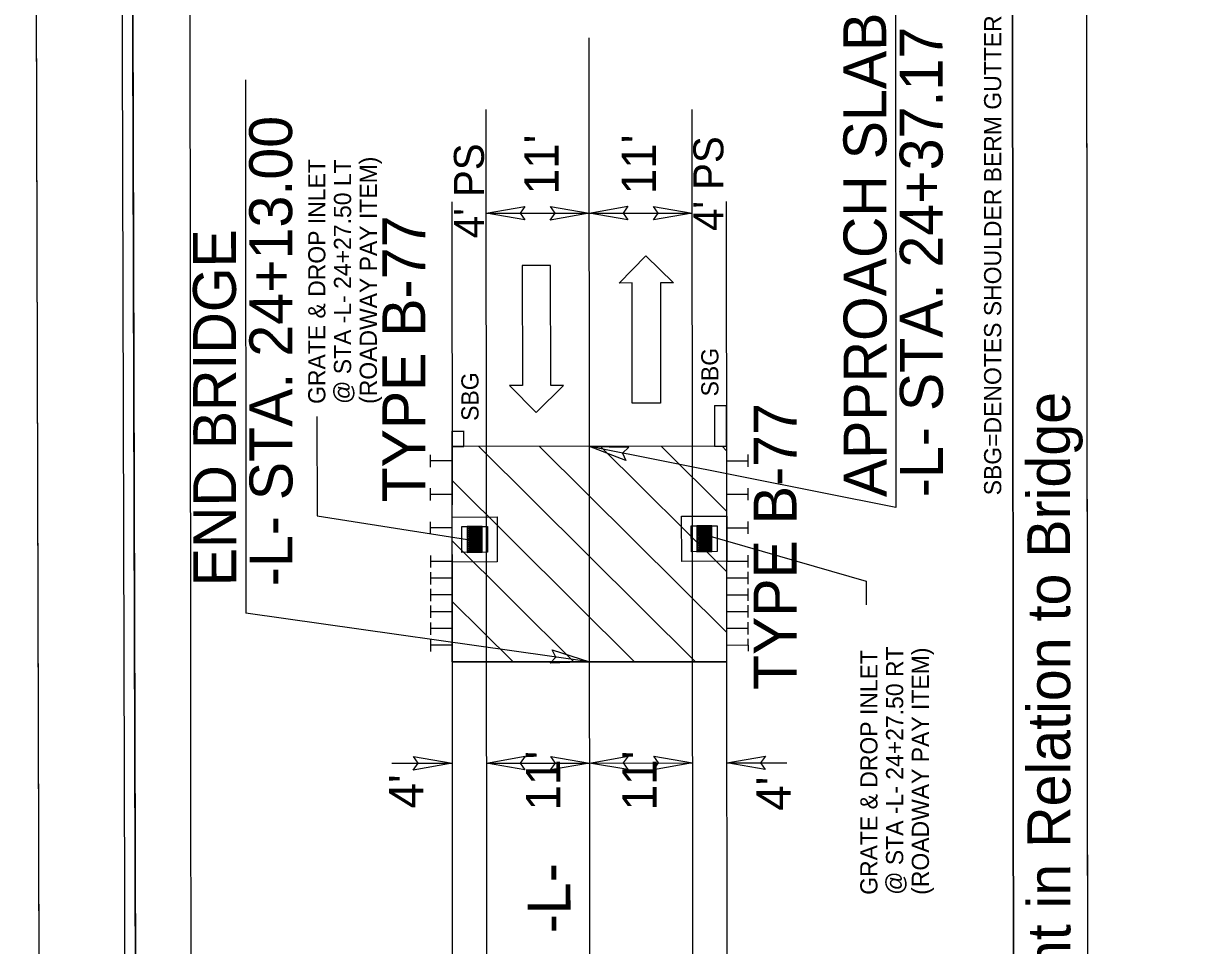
# Model space of a CAD drawing. Extents: x 1373110 to 1374209, y 550682 to 552749.
# Drawn here: x 1373109.6 to 1373384.5, y 551240.4 to 551455.3 of the extents above; entities that cross this region are included whole.
import ezdxf

# ---------------------------------------------------------------- set-up
doc = ezdxf.new("R2010")
doc.units = 0
for name, color, linetype in [('Default', 7, 'Continuous'), ('Prop Approach Slab Hatching', 7, 'Continuous'), ('Prop Drainage Structure Drop Inlet Grate 2 Narrow Slots and Flat Grates 840 29 TB Label', 7, 'Continuous'), ('Prop Drainage Structure Gutter Shoulder Berm Label', 7, 'Continuous'), ('Prop Drainage Structure Pipe Alternate 18in', 7, 'Continuous'), ('Prop Drainage Structure Pipe Alternate 18in Label', 7, 'Continuous'), ('Prop Drainage Structure Pipe CSP 15in Label', 7, 'Continuous'), ('Prop Drainage Structure Pipe RCP 15in Class IV Label', 7, 'Continuous'), ('Prop Drainage Structure Pipe Removal Label', 7, 'Continuous'), ('Prop Drainage Structure Tops and Inverts LABEL', 7, 'Continuous'), ('Prop Earthen Structure Base Ditch with Rip Rap Detail CELL', 7, 'Continuous'), ('Prop Earthen Structure Base Ditch with Rip Rap Detail Label', 7, 'Continuous'), ('Prop Earthen Structure V Ditch Special Lateral Detail Label', 7, 'Continuous'), ('Prop Erosion Rip Rap At Embankment Detail CELL', 7, 'Continuous'), ('Prop Erosion Rip Rap At Embankment Detail Label', 7, 'Continuous'), ('Prop Erosion Rip Rap Class B Label', 7, 'Continuous'), ('Prop Erosion Rip Rap Class I', 7, 'Continuous'), ('Prop Plan Preparation Sketches Hydraulic Ditch', 7, 'Continuous'), ('Prop Roadway Bridge', 7, 'Continuous'), ('Prop SS Fill Line', 7, 'Continuous')]:
    doc.layers.add(name, color=color, linetype=linetype)

msp = doc.modelspace()

# ---------------------------------------------------------------- linework, layer by layer
at = {"layer": 'Default'}
for p, q in [((1373216.4, 551338.01), (1373212.9, 551338)), ((1373212.9, 551338), (1373212.91, 551332)), ((1373212.99, 551337.91), (1373216.3, 551337.92)), ((1373213.01, 551332.1), (1373212.99, 551337.91)), ((1373216.29, 551337.9), (1373213, 551337.89)), ((1373213, 551337.89), (1373213.01, 551335.02)), ((1373213.28, 551337.38), (1373213.28, 551337.65)), ((1373213.28, 551337.65), (1373216.01, 551337.65)), ((1373216.01, 551337.39), (1373213.28, 551337.38)), ((1373213.28, 551337.2), (1373216.01, 551337.21)), ((1373213.28, 551336.93), (1373213.28, 551337.2)), ((1373214.65, 551338.01), (1373214.65, 551338.01)), ((1373216.01, 551337.65), (1373216.01, 551337.39)), ((1373216.01, 551337.21), (1373216.02, 551336.94)), ((1373216.29, 551335.03), (1373216.29, 551337.9)), ((1373216.3, 551337.92), (1373216.32, 551332.11)), ((1373216.41, 551332.01), (1373216.4, 551338.01)), ((1373269.9, 551338.17), (1373266.4, 551338.16)), ((1373266.4, 551338.16), (1373266.41, 551332.16)), ((1373266.49, 551338.07), (1373269.8, 551338.08)), ((1373266.51, 551332.26), (1373266.49, 551338.07)), ((1373269.79, 551338.06), (1373266.5, 551338.05)), ((1373266.5, 551338.05), (1373266.51, 551335.18)), ((1373266.78, 551337.8), (1373269.51, 551337.81)), ((1373266.78, 551337.54), (1373266.78, 551337.8)), ((1373269.51, 551337.55), (1373266.78, 551337.54)), ((1373266.78, 551337.36), (1373269.51, 551337.37)), ((1373266.78, 551337.09), (1373266.78, 551337.36)), ((1373268.15, 551338.17), (1373268.15, 551338.17)), ((1373269.51, 551337.81), (1373269.51, 551337.55)), ((1373269.51, 551337.37), (1373269.52, 551337.1)), ((1373269.79, 551335.19), (1373269.79, 551338.06)), ((1373269.8, 551338.08), (1373269.82, 551332.27)), ((1373269.91, 551332.17), (1373269.9, 551338.17)), ((1373212.9, 551335), (1373212.9, 551335)), ((1373213.01, 551335.02), (1373216.29, 551335.03)), ((1373216.29, 551335), (1373213.01, 551334.99)), ((1373213.01, 551334.99), (1373213.02, 551332.11)), ((1373216.02, 551336.94), (1373213.28, 551336.93)), ((1373213.28, 551336.75), (1373216.02, 551336.76)), ((1373213.28, 551336.49), (1373213.28, 551336.75)), ((1373216.02, 551336.5), (1373213.28, 551336.49)), ((1373213.28, 551336.31), (1373216.02, 551336.32)), ((1373213.28, 551336.04), (1373213.28, 551336.31)), ((1373216.02, 551336.05), (1373213.28, 551336.04)), ((1373213.28, 551335.86), (1373216.02, 551335.87)), ((1373213.28, 551335.6), (1373213.28, 551335.86)), ((1373216.02, 551335.61), (1373213.28, 551335.6)), ((1373213.29, 551335.42), (1373216.02, 551335.43)), ((1373213.29, 551335.15), (1373213.29, 551335.42)), ((1373216.02, 551335.16), (1373213.29, 551335.15)), ((1373213.29, 551334.59), (1373213.29, 551334.86)), ((1373213.29, 551334.86), (1373216.02, 551334.86)), ((1373216.02, 551334.6), (1373213.29, 551334.59)), ((1373213.29, 551334.41), (1373216.02, 551334.42)), ((1373213.29, 551334.15), (1373213.29, 551334.41)), ((1373214.65, 551335.01), (1373214.65, 551335.01)), ((1373216.02, 551336.76), (1373216.02, 551336.5)), ((1373216.02, 551336.32), (1373216.02, 551336.05)), ((1373216.02, 551335.87), (1373216.02, 551335.61)), ((1373216.02, 551335.43), (1373216.02, 551335.16)), ((1373216.02, 551334.86), (1373216.02, 551334.6)), ((1373216.02, 551334.42), (1373216.02, 551334.15)), ((1373216.3, 551332.12), (1373216.29, 551335)), ((1373216.4, 551335.01), (1373216.4, 551335.01)), ((1373266.4, 551335.16), (1373266.4, 551335.16)), ((1373266.51, 551335.18), (1373269.79, 551335.19)), ((1373269.79, 551335.16), (1373266.51, 551335.15)), ((1373266.51, 551335.15), (1373266.52, 551332.27)), ((1373269.52, 551337.1), (1373266.78, 551337.09)), ((1373266.78, 551336.91), (1373269.52, 551336.92)), ((1373266.78, 551336.65), (1373266.78, 551336.91)), ((1373269.52, 551336.66), (1373266.78, 551336.65)), ((1373266.78, 551336.47), (1373269.52, 551336.48)), ((1373266.78, 551336.2), (1373266.78, 551336.47)), ((1373269.52, 551336.21), (1373266.78, 551336.2)), ((1373266.78, 551336.02), (1373269.52, 551336.03)), ((1373266.78, 551335.76), (1373266.78, 551336.02)), ((1373269.52, 551335.77), (1373266.78, 551335.76)), ((1373266.79, 551335.58), (1373269.52, 551335.59)), ((1373266.79, 551335.31), (1373266.79, 551335.58)), ((1373269.52, 551335.32), (1373266.79, 551335.31)), ((1373266.79, 551334.75), (1373266.79, 551335.02)), ((1373266.79, 551335.02), (1373269.52, 551335.02)), ((1373269.52, 551334.76), (1373266.79, 551334.75)), ((1373266.79, 551334.57), (1373269.52, 551334.58)), ((1373266.79, 551334.3), (1373266.79, 551334.57)), ((1373268.15, 551335.17), (1373268.15, 551335.17)), ((1373269.52, 551336.92), (1373269.52, 551336.66)), ((1373269.52, 551336.48), (1373269.52, 551336.21)), ((1373269.52, 551336.03), (1373269.52, 551335.77)), ((1373269.52, 551335.59), (1373269.52, 551335.32)), ((1373269.52, 551335.02), (1373269.52, 551334.76)), ((1373269.52, 551334.58), (1373269.52, 551334.31)), ((1373269.8, 551332.28), (1373269.79, 551335.16)), ((1373269.9, 551335.17), (1373269.9, 551335.17)), ((1373212.91, 551332), (1373216.41, 551332.01)), ((1373216.32, 551332.11), (1373213.01, 551332.1)), ((1373213.02, 551332.11), (1373216.3, 551332.12)), ((1373216.02, 551334.15), (1373213.29, 551334.15)), ((1373213.29, 551333.7), (1373213.29, 551333.97)), ((1373213.29, 551333.97), (1373216.02, 551333.97)), ((1373216.02, 551333.71), (1373213.29, 551333.7)), ((1373213.29, 551333.52), (1373216.02, 551333.53)), ((1373213.29, 551333.26), (1373213.29, 551333.52)), ((1373216.03, 551333.26), (1373213.29, 551333.26)), ((1373213.29, 551332.81), (1373213.29, 551333.08)), ((1373213.29, 551333.08), (1373216.03, 551333.08)), ((1373216.03, 551332.82), (1373213.29, 551332.81)), ((1373213.29, 551332.63), (1373216.03, 551332.64)), ((1373213.29, 551332.36), (1373213.29, 551332.63)), ((1373216.03, 551332.37), (1373213.29, 551332.36)), ((1373214.66, 551332.01), (1373214.66, 551332.01)), ((1373216.02, 551333.97), (1373216.02, 551333.71)), ((1373216.02, 551333.53), (1373216.03, 551333.26)), ((1373216.03, 551333.08), (1373216.03, 551332.82)), ((1373216.03, 551332.64), (1373216.03, 551332.37)), ((1373266.41, 551332.16), (1373269.91, 551332.17)), ((1373269.82, 551332.27), (1373266.51, 551332.26)), ((1373266.52, 551332.27), (1373269.8, 551332.28)), ((1373269.52, 551334.31), (1373266.79, 551334.3)), ((1373266.79, 551334.12), (1373269.52, 551334.13)), ((1373266.79, 551333.86), (1373266.79, 551334.12)), ((1373269.52, 551333.87), (1373266.79, 551333.86)), ((1373266.79, 551333.68), (1373269.52, 551333.69)), ((1373266.79, 551333.41), (1373266.79, 551333.68)), ((1373269.53, 551333.42), (1373266.79, 551333.41)), ((1373266.79, 551333.23), (1373269.53, 551333.24)), ((1373266.79, 551332.97), (1373266.79, 551333.23)), ((1373269.53, 551332.98), (1373266.79, 551332.97)), ((1373266.79, 551332.79), (1373269.53, 551332.8)), ((1373266.79, 551332.52), (1373266.79, 551332.79)), ((1373269.53, 551332.53), (1373266.79, 551332.52)), ((1373268.16, 551332.17), (1373268.16, 551332.17)), ((1373269.52, 551334.13), (1373269.52, 551333.87)), ((1373269.52, 551333.69), (1373269.53, 551333.42)), ((1373269.53, 551333.24), (1373269.53, 551332.98)), ((1373269.53, 551332.8), (1373269.53, 551332.53))]:
    msp.add_line(p, q, dxfattribs=at)
for points in [[(1373219.89, 551340.27), (1373219.92, 551329.77), (1373209.42, 551329.74), (1373209.39, 551340.24)], [(1373273.39, 551340.43), (1373273.42, 551329.93), (1373262.92, 551329.9), (1373262.89, 551340.4)], [(1373217.65, 551338.02), (1373217.66, 551332.02), (1373211.66, 551332), (1373211.65, 551338)], [(1373271.15, 551338.18), (1373271.16, 551332.18), (1373265.16, 551332.16), (1373265.15, 551338.16)]]:
    msp.add_lwpolyline(points, close=True, dxfattribs=at)
at = {"layer": 'Prop Approach Slab Hatching'}
for p, q in [((1373273.44, 551306.49), (1373209.4, 551306.44)), ((1373209.4, 551306.44), (1373209.49, 551206.85)), ((1373273.53, 551206.9), (1373273.44, 551306.49))]:
    msp.add_line(p, q, dxfattribs=at)
at = {"layer": 'Prop Drainage Structure Drop Inlet Grate 2 Narrow Slots and Flat Grates 840 29 TB Label'}
for points in [[(1373132.1, 552509.76), (1373136.2, 551009.73), (1374186.2, 551012.6), (1374182.1, 552512.6)], [(1374186.2, 551012.6), (1373136.23, 551009.7), (1373132.64, 552309.68), (1373282.7, 552310.11), (1373282.16, 552510.14), (1374182.1, 552512.6)]]:
    msp.add_lwpolyline(points, close=True, dxfattribs=at)
at = {"layer": 'Prop Drainage Structure Gutter Shoulder Berm Label'}
msp.add_lwpolyline([(1374209.17, 550846.17), (1374204.56, 552529.67), (1373109.57, 552526.67), (1373114.17, 550843.18)], close=True, dxfattribs=at)
at = {"layer": 'Prop Drainage Structure Pipe Alternate 18in'}
for p, q in [((1373204.4, 551351.88), (1373204.4, 551354.74)), ((1373278.4, 551351.94), (1373278.4, 551354.81)), ((1373209.4, 551353.31), (1373204.4, 551353.31)), ((1373209.44, 551306.44), (1373209.4, 551353.31)), ((1373273.4, 551353.37), (1373278.4, 551353.37)), ((1373273.44, 551306.49), (1373273.4, 551353.37)), ((1373204.41, 551344.06), (1373204.4, 551346.93)), ((1373209.4, 551345.5), (1373204.4, 551345.5)), ((1373273.4, 551345.56), (1373278.4, 551345.56)), ((1373278.41, 551344.13), (1373278.4, 551346.99)), ((1373204.41, 551336.25), (1373204.41, 551339.12)), ((1373209.41, 551337.69), (1373204.41, 551337.68)), ((1373273.41, 551337.74), (1373278.41, 551337.75)), ((1373278.41, 551336.32), (1373278.41, 551339.18)), ((1373204.42, 551328.44), (1373204.42, 551331.3)), ((1373209.42, 551329.88), (1373204.42, 551329.87)), ((1373273.42, 551329.93), (1373278.42, 551329.94)), ((1373278.42, 551328.5), (1373278.42, 551331.37)), ((1373204.42, 551324.53), (1373204.42, 551327.4)), ((1373278.42, 551324.6), (1373278.42, 551327.46)), ((1373209.42, 551325.97), (1373204.42, 551325.96)), ((1373204.43, 551320.63), (1373204.42, 551323.49)), ((1373273.42, 551326.03), (1373278.42, 551326.03)), ((1373278.43, 551320.69), (1373278.42, 551323.56)), ((1373209.42, 551322.06), (1373204.42, 551322.06)), ((1373273.42, 551322.12), (1373278.42, 551322.12)), ((1373204.43, 551316.72), (1373204.43, 551319.58)), ((1373209.43, 551318.16), (1373204.43, 551318.15)), ((1373273.43, 551318.21), (1373278.43, 551318.22)), ((1373278.43, 551316.79), (1373278.43, 551319.65)), ((1373204.43, 551312.81), (1373204.43, 551315.68)), ((1373278.43, 551312.88), (1373278.43, 551315.74)), ((1373209.43, 551314.25), (1373204.43, 551314.25)), ((1373273.43, 551314.31), (1373278.43, 551314.31)), ((1373204.44, 551308.91), (1373204.43, 551311.77)), ((1373209.43, 551310.34), (1373204.43, 551310.34)), ((1373273.43, 551310.4), (1373278.43, 551310.41)), ((1373278.44, 551308.97), (1373278.43, 551311.84))]:
    msp.add_line(p, q, dxfattribs=at)
at = {"layer": 'Prop Drainage Structure Pipe Alternate 18in Label'}
for points in [[(1373226.35, 551409.52), (1373217.35, 551411.06), (1373226.39, 551412.67), (1373225.25, 551411.07)], [(1373232.34, 551412.62), (1373241.35, 551411.08), (1373232.3, 551409.47), (1373233.45, 551411.07)], [(1373250.35, 551409.54), (1373241.35, 551411.08), (1373250.39, 551412.69), (1373249.25, 551411.09)], [(1373256.34, 551412.64), (1373265.35, 551411.1), (1373256.3, 551409.49), (1373257.45, 551411.09)], [(1373249.92, 551353.42), (1373241.39, 551356.7), (1373250.58, 551356.5), (1373249.14, 551355.16)], [(1373232.74, 551309.26), (1373241.44, 551306.47), (1373232.25, 551306.15), (1373233.62, 551307.57)], [(1373200.38, 551284.4), (1373209.39, 551282.86), (1373200.34, 551281.25), (1373201.49, 551282.85)], [(1373226.39, 551281.32), (1373217.39, 551282.86), (1373226.43, 551284.47), (1373225.29, 551282.87)], [(1373232.38, 551284.43), (1373241.39, 551282.88), (1373232.34, 551281.28), (1373233.49, 551282.88)], [(1373250.39, 551281.34), (1373241.39, 551282.88), (1373250.43, 551284.49), (1373249.29, 551282.89)], [(1373256.38, 551284.45), (1373265.39, 551282.9), (1373256.34, 551281.3), (1373257.49, 551282.9)], [(1373282.39, 551281.37), (1373273.39, 551282.91), (1373282.43, 551284.52), (1373281.29, 551282.92)]]:
    msp.add_lwpolyline(points, close=True, dxfattribs=at)
at = {"layer": 'Prop Drainage Structure Pipe CSP 15in Label'}
msp.add_line((1373109.57, 552526.67), (1373114.17, 550843.18), dxfattribs=at)
at = {"layer": 'Prop Drainage Structure Pipe RCP 15in Class IV Label'}
msp.add_lwpolyline([(1373136.23, 551009.7), (1374186.2, 551012.6), (1374182.1, 552512.59), (1373343.59, 552510.3), (1373344.24, 552271.05), (1373132.76, 552270.47)], close=True, dxfattribs=at)
at = {"layer": 'Prop Drainage Structure Pipe Removal Label'}
for p, q in [((1373209.34, 551413.72), (1373209.41, 551343.09)), ((1373273.41, 551343.15), (1373273.34, 551413.77))]:
    msp.add_line(p, q, dxfattribs=at)
at = {"layer": 'Prop Drainage Structure Tops and Inverts LABEL'}
msp.add_lwpolyline([(1374189.13, 550859.12), (1374184.56, 552525.1), (1373129.58, 552522.23), (1373134.14, 550856.23)], close=True, dxfattribs=at)
at = {"layer": 'Prop Earthen Structure Base Ditch with Rip Rap Detail CELL'}
msp.add_lwpolyline([(1374186.06, 551062.6), (1374182.23, 552462.6), (1373343.73, 552460.31), (1373344.24, 552271.05), (1373132.76, 552270.47), (1373136.07, 551059.72)], close=True, dxfattribs=at)
at = {"layer": 'Prop Earthen Structure Base Ditch with Rip Rap Detail Label'}
for p, q in [((1373177.89, 551363.69), (1373177.95, 551340.49)), ((1373177.95, 551340.49), (1373213.01, 551335.02)), ((1373269.52, 551335.77), (1373305.87, 551325.25)), ((1373305.87, 551325.25), (1373305.89, 551319.74))]:
    msp.add_line(p, q, dxfattribs=at)
at = {"layer": 'Prop Earthen Structure V Ditch Special Lateral Detail Label'}
for p, q in [((1373217.64, 551078.27), (1373217.32, 551435.22)), ((1373265.64, 551078.31), (1373265.32, 551435.27))]:
    msp.add_line(p, q, dxfattribs=at)
at = {"layer": 'Prop Erosion Rip Rap At Embankment Detail CELL'}
for p, q in [((1373270.54, 551366.24), (1373273.37, 551366.25)), ((1373270.54, 551366.24), (1373270.57, 551356.72)), ((1373273.36, 551356.73), (1373273.35, 551366.25)), ((1373209.35, 551360.22), (1373209.36, 551356.67)), ((1373209.39, 551360.22), (1373212.21, 551360.22)), ((1373212.15, 551356.68), (1373212.14, 551360.22)), ((1373209.36, 551356.67), (1373212.15, 551356.68)), ((1373270.57, 551356.72), (1373273.36, 551356.73))]:
    msp.add_line(p, q, dxfattribs=at)
at = {"layer": 'Prop Erosion Rip Rap At Embankment Detail Label'}
for p, q in [((1373273.39, 551356.73), (1373209.36, 551356.67)), ((1373209.36, 551356.67), (1373209.4, 551306.44)), ((1373273.44, 551306.49), (1373273.39, 551356.73)), ((1373209.4, 551306.44), (1373273.44, 551306.49)), ((1373273.44, 551306.49), (1373209.44, 551306.44))]:
    msp.add_line(p, q, dxfattribs=at)
at = {"layer": 'Prop Erosion Rip Rap Class B Label'}
for points in [[(1374186.06, 551062.6), (1374182.23, 552462.6), (1373343.73, 552460.31), (1373344.24, 552271.05), (1373132.76, 552270.47), (1373136.07, 551059.72)], [(1374186.13, 551055.1), (1374185.31, 551891.66), (1374039.33, 551891.53), (1374038.82, 552461.52), (1373346.29, 552460.9), (1373346.46, 552271.64), (1373134.97, 552271.45), (1373135.76, 551468.67), (1373357.23, 551468.89), (1373357.64, 551054.29)]]:
    msp.add_lwpolyline(points, close=True, dxfattribs=at)
at = {"layer": 'Prop Erosion Rip Rap Class I'}
for p, q in [((1373248.37, 551394.79), (1373254.57, 551401.1)), ((1373254.57, 551401.1), (1373260.97, 551394.8)), ((1373225.75, 551398.89), (1373225.78, 551370.89)), ((1373232.35, 551398.89), (1373225.75, 551398.89)), ((1373232.38, 551370.89), (1373232.35, 551398.89)), ((1373251.37, 551394.8), (1373248.37, 551394.79)), ((1373251.4, 551366.8), (1373251.37, 551394.8)), ((1373260.97, 551394.8), (1373257.97, 551394.8)), ((1373257.97, 551394.8), (1373258, 551366.8)), ((1373225.78, 551370.89), (1373222.78, 551370.88)), ((1373222.78, 551370.88), (1373228.99, 551364.59)), ((1373228.99, 551364.59), (1373235.38, 551370.89)), ((1373235.38, 551370.89), (1373232.38, 551370.89)), ((1373258, 551366.8), (1373251.4, 551366.8))]:
    msp.add_line(p, q, dxfattribs=at)
at = {"layer": 'Prop Plan Preparation Sketches Hydraulic Ditch'}
for p, q in [((1373312.7, 551466.02), (1373312.81, 551342.47)), ((1373161.27, 551442.19), (1373161.38, 551317.8)), ((1373217.35, 551411.06), (1373241.35, 551411.08)), ((1373241.35, 551411.08), (1373265.35, 551411.1)), ((1373312.81, 551342.47), (1373241.39, 551356.7)), ((1373241.44, 551306.47), (1373161.38, 551317.8)), ((1373195.39, 551282.84), (1373209.39, 551282.86)), ((1373217.39, 551282.86), (1373241.39, 551282.88)), ((1373241.39, 551282.88), (1373265.39, 551282.9)), ((1373273.39, 551282.91), (1373287.39, 551282.92))]:
    msp.add_line(p, q, dxfattribs=at)
for points in [[(1373148.78, 551044.12), (1373148.41, 551468.7), (1373340.01, 551468.88), (1373340.39, 551044.29)], [(1373340.39, 551044.29), (1373340.01, 551468.88), (1373357.23, 551468.89), (1373357.61, 551044.31)]]:
    msp.add_lwpolyline(points, close=True, dxfattribs=at)
at = {"layer": 'Prop Roadway Bridge'}
msp.add_line((1373241.66, 551054.35), (1373241.31, 551451.98), dxfattribs=at)
at = {"layer": 'Prop SS Fill Line'}
for p, q in [((1373266.11, 551306.49), (1373215.65, 551356.68)), ((1373273.43, 551313.32), (1373229.81, 551356.69)), ((1373273.4, 551327.44), (1373243.98, 551356.7)), ((1373273.38, 551341.57), (1373258.15, 551356.72)), ((1373273.36, 551355.7), (1373272.32, 551356.73)), ((1373251.94, 551306.48), (1373209.37, 551348.82)), ((1373223.55, 551320.61), (1373209.39, 551334.69)), ((1373216.49, 551313.53), (1373209.42, 551320.56)), ((1373237.78, 551306.46), (1373223.56, 551320.61)), ((1373223.61, 551306.45), (1373216.5, 551313.52)), ((1373209.44, 551306.44), (1373209.42, 551306.46)), ((1373209.44, 551306.44), (1373209.44, 551306.44))]:
    msp.add_line(p, q, dxfattribs=at)

# ---------------------------------------------------------------- texts
at = {"layer": 'Prop Drainage Structure Pipe Alternate 18in'}
for p in [(1373203.17, 551343.64), (1373289.67, 551299.92)]:
    msp.add_text('TYPE B-77', height=10, rotation=90, dxfattribs=at).set_placement(p)
at = {"layer": 'Prop Earthen Structure Base Ditch with Rip Rap Detail Label'}
for s, height, rotation, p in [('APPROACH SLAB', 10, 90.0509, (1373310.66, 551344.88)), ('SBG=DENOTES SHOULDER BERM GUTTER', 4, 90, (1373337.36, 551345.3)), ('-L- STA. 24+37.17               ', 10, 90.0509, (1373323.77, 551344.89)), ('-L- STA. 24+13.00        ', 10, 90.0509, (1373172.22, 551324.12)), ('GRATE & DROP INLET', 4, 90, (1373179.88, 551366.61)), ('@ STA -L- 24+27.50 LT', 4, 90, (1373185.88, 551366.61)), ('(ROADWAY PAY ITEM)', 4, 90, (1373191.88, 551366.61)), ('END BRIDGE', 10, 90.0509, (1373159.11, 551324.11)), ('SBG', 4, 90, (1373271.47, 551368.37)), ('SBG', 4, 90, (1373215.57, 551362.66)), ('Sketch of Pavement in Relation to Bridge', 10, 90.0509, (1373353.59, 551125.6)), ('@ STA -L- 24+27.50 RT', 4, 90, (1373314.52, 551252.16)), ('GRATE & DROP INLET', 4, 90, (1373308.52, 551252.16)), ('(ROADWAY PAY ITEM)', 4, 90, (1373320.52, 551252.16)), ('-L-', 10, 90.1567, (1373237.02, 551243.18))]:
    msp.add_text(s, height=height, rotation=rotation, dxfattribs=at).set_placement(p)
at = {"layer": 'Prop Plan Preparation Sketches Hydraulic Ditch'}
for s, height, p in [("11'", 8, (1373234.22, 551415.46)), ("11'", 8, (1373256.91, 551415.48)), ("4' PS", 7, (1373272.64, 551406.93)), ("4' PS", 7, (1373216.85, 551405.26)), ("11'", 8, (1373234.6, 551271.81)), ("11'", 8, (1373257.05, 551271.83)), ("4'", 8, (1373202.68, 551272.28)), ("4'", 8, (1373288.33, 551271.74))]:
    msp.add_text(s, height=height, rotation=90.0509, dxfattribs=at).set_placement(p)

doc.saveas('drawing.dxf')
